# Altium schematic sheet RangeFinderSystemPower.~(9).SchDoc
size A; DocumentNumber: 6; SheetNumber: 6; SheetTotal: 6
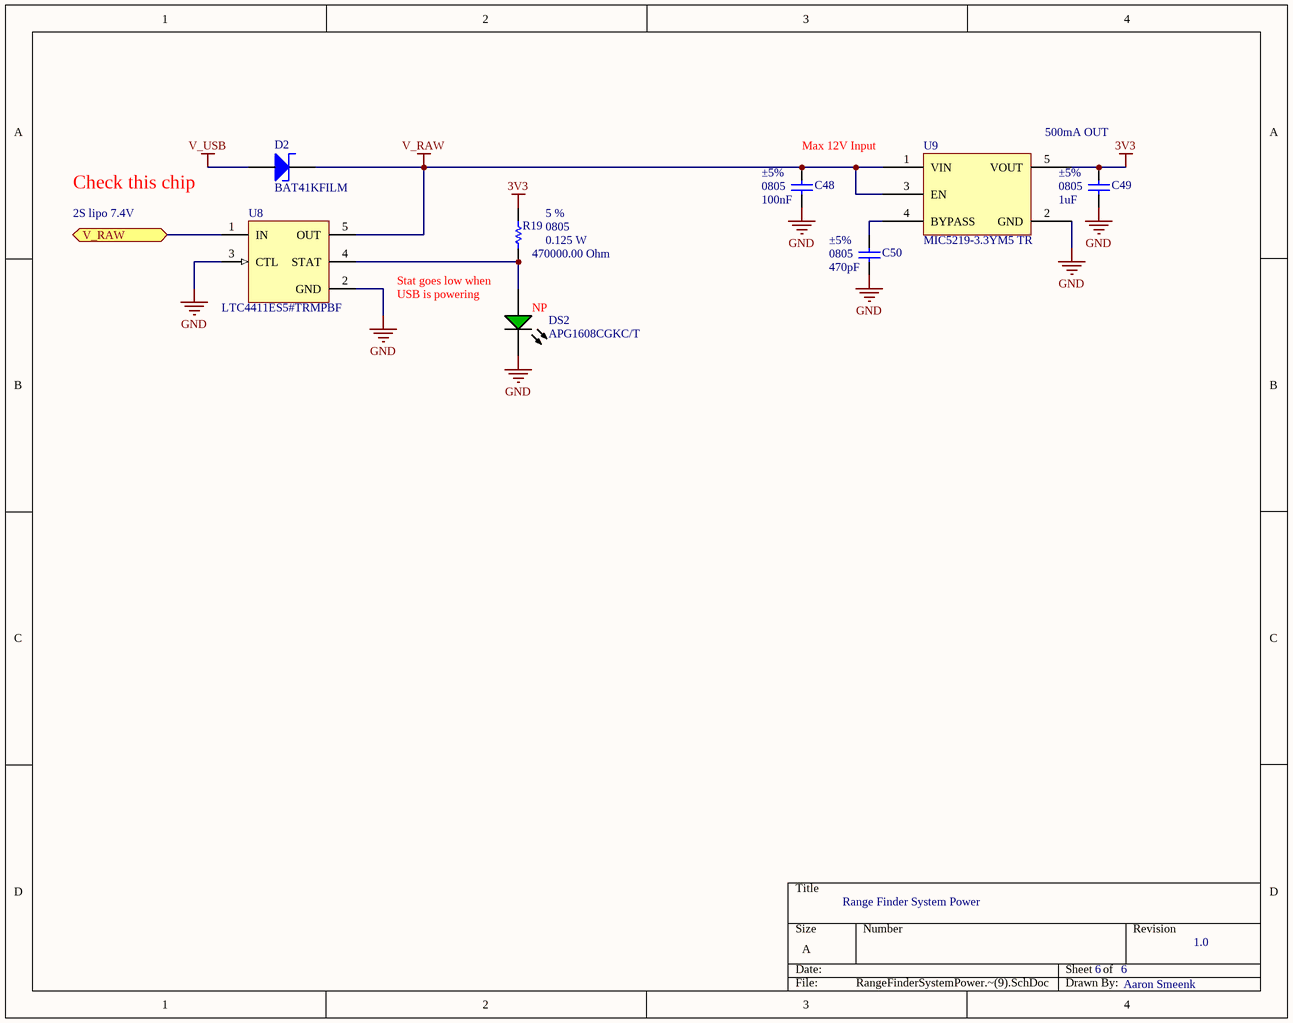
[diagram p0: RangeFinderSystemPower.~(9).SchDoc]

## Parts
C48  value 100nF  Tolerance: ±5%  Case-EIA: 0805  [CAPC0805(2012)100_L]  (hidden comment: CAP 100nF 6.3V 0805(2012))
C49  value 1uF  Tolerance: ±5%  Case-EIA: 0805  [CAPC0805(2012)100_M]  (hidden comment: CAP 1uF 6.3V 0805(2012))
C50  value 470pF  Case-EIA: 0805  Tolerance: ±5%  [CAPC0805(2012)100_L]  (hidden comment: CAP 470pF 6.3V 0805(2012))
D2  BAT41KFILM  [BAT41KFILM]
DS2  APG1608CGKC/T  [KING-LED0603-25-GREEN_V]
R19  value 470000.00 Ohm  Power: 0.125 W  Tolerance: 5 %  Case-EIA: 0805  [RESC0805(2012)_M]  (hidden comment: 470K 5% 0805(2012))
U8  LTC4411ES5#TRMPBF  [LT-S5-5-TSOT-23_N]
U9  MIC5219-3.3YM5 TR

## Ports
V_RAW

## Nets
3V3: C49.2 R19.2 U9.5(VOUT)
GND: C48.1 C49.1 C50.1 DS2.2(K) U8.2(GND) U8.3(CTL) U9.2(GND)
V_RAW: C48.2 D2.1 U8.5(OUT) U9.1(VIN) U9.3(EN)
V_USB: D2.2
V_RAW: U8.1(IN) ; port V_RAW  [a separate net that carries the same name]
NetC50_2: C50.2 U9.4(BYPASS)
NetDS2_1: DS2.1(A) R19.1 U8.4(STAT)

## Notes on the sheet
- (near C48) Max 12V Input
- 500mA OUT
- 2S lipo 7.4V
- Check this chip
- Stat goes low when
- USB is powering
- (near DS2) NP
- Range Finder System Power
- 6
- 1.0
- Aaron Smeenk

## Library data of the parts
C48 = CMP-1036-04390-1: CAP 100nF 6.3V ±5% 0805 (2012 Metric) Thickness 1mm SMD; Case-Metric: 2012
C49 = CMP-1036-04730-1: CAP 1uF 6.3V ±5% 0805 (2012 Metric) Thickness 1mm SMD; Case-Metric: 2012
C50 = CMP-1036-02639-1: CAP 470pF 6.3V ±5% 0805 (2012 Metric) Thickness 1mm SMD; Case-Metric: 2012
D2 = BAT41KFILM: DIODE SCHOTTKY 100V 200MA SOD523; Current - Average Rectified (Io): 200mA (DC); Voltage - Forward (Vf) (Max) @ If: 1V @ 200mA; Speed: Small Signal =< 200mA (Io), Any Speed; Current - Reverse Leakage @ Vr: 100nA @ 50V; Capacitance @ Vr, F: 10pF @ 1V, 1MHz
DS2 = CMP-0239-00001-1: LED, SMT, 0603(1608), 0.25mm Thickness, Green; Forward Current: 30 mA; Reverse Voltage: 5 V; Power Dissipation: 78 mW; Packing: Reel
R19 = CMP-1013-00138-1: 470K 0.125W 5% 0805 (2012 Metric)  SMD; Case-Metric: 2012
U8 = CMP-0479-00414-1: Integrated Switch: Replaces Power Supply OR, 2.6 to 5.5 V Vin, 5-pin SOT23 (S5-5), -40 to 85 degC, Pb-Free, Mini Tape and Reel; Manufacturer: Linear Technology; Ideal Diode: Single, Internal, P-Channel
U9 = MIC5219-3.3YM5 TR: IC REG LDO 3.3V 0.5A SOT23-5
